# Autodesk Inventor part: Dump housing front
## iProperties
Created: 2008-09
Part Number: Dump housing front
Document SubType Name: Modeling
Designer: the-dude
Density: 1 g/cm^3
Author: the-dude
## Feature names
1. Housing outline [Revolution]
2. Tie screw hole (1/4-28) [Revolution]
3. Tie screw threads 1/4-28
4. Tie screw hole array [Circular Pattern]
5. Solenoid output hole (10-32) [Revolution]
6. Solenoid output hole threads 10-32
7. Solenoid output hole lateral [Revolution]
8. 10-32 Solenoid hole lateral threads
9. Poppet vent hole (10-32) [Revolution]
10. Poppet vent hole threads 10-32 [Mirror]
11. Poppet vent hole lateral [Revolution]
12. Interpolated text outline 1 [Revolution]
13. Interpolated text outline 2 [Rectangular Pattern]
14. Interpolated text outline 3 [Extrusion]
15. Solenoid output T-slot (optional) [Extrusion]
16. Poppet vent T-slot (optional) [Extrusion]
17. Barrel screw hole [Revolution]
18. Barrel screw hole threads 6-32
